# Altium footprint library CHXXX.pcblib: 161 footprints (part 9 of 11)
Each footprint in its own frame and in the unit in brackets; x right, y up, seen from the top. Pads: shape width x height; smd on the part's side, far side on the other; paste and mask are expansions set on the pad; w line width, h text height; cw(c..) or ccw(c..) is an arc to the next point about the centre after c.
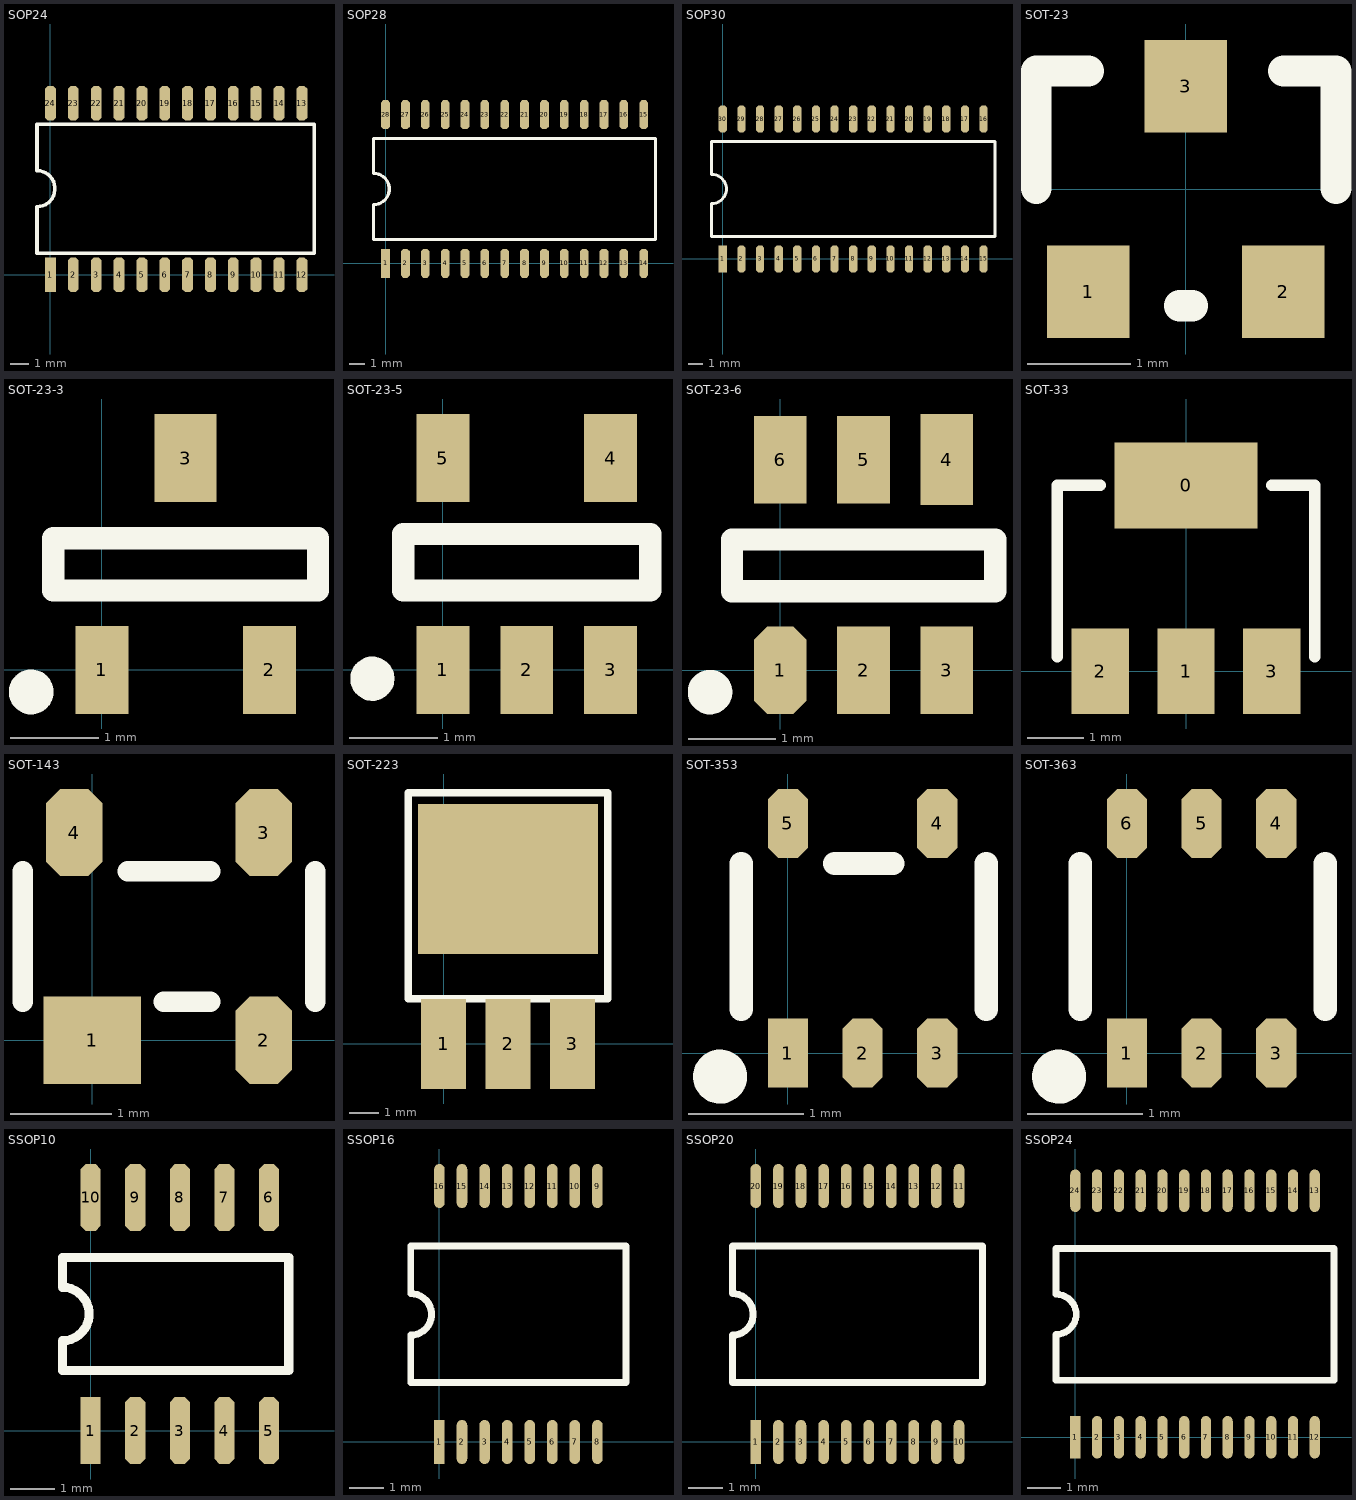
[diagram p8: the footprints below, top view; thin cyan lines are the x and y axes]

## SOP24 [mm]
pads (24):
  rect 0.6x1.905 smd: 1(0,0)
  oct 0.6x1.905 smd: 2(1.27,0) 3(2.54,0) 4(3.81,0) 5(5.08,0) 6(6.35,0) 7(7.62,0) 8(8.89,0) 9(10.16,0) 10(11.43,0) 11(12.7,0) 12(13.97,0) 13(13.97,9.525) 14(12.7,9.525) 15(11.43,9.525) 16(10.16,9.525) 17(8.89,9.525) 18(7.62,9.525) 19(6.35,9.525) 20(5.08,9.525) 21(3.81,9.525) 22(2.54,9.525) 23(1.27,9.525) 24(0,9.525)
TopOverlay:
  lines w0.2: -0.747,1.191 -0.747,3.78 ccw(c-0.747,4.78) -0.747,5.78 -0.747,8.368 14.653,8.368 14.653,1.191 -0.747,1.191

## SOP28 [mil]
pads (28):
  rect 22x72 smd: 1(0,0)
  oct 22x72 smd: 2(50,0) 3(100,0) 4(150,0) 5(200,0) 6(250,0) 7(300,0) 8(350,0) 9(400,0) 10(450,0) 11(500,0) 12(550,0) 13(600,0) 14(650,0) 15(650,375) 16(600,375) 17(550,375) 18(500,375) 19(450,375) 20(400,375) 21(350,375) 22(300,375) 23(250,375) 24(200,375) 25(150,375) 26(100,375) 27(50,375) 28(0,375)
TopOverlay:
  lines w8: -30,147.63 -30,60 680,60 680,315 -30,315 -30,226.87 cw(c-30,187.5) -30,148.13

## SOP30 [mil]
pads (30):
  rect 22x72 smd: 1(0,0)
  oct 22x72 smd: 2(50,0) 3(100,0) 4(150,0) 5(200,0) 6(250,0) 7(300,0) 8(350,0) 9(400,0) 10(450,0) 11(500,0) 12(550,0) 13(600,0) 14(650,0) 15(700,0) 16(700,375) 17(650,375) 18(600,375) 19(550,375) 20(500,375) 21(450,375) 22(400,375) 23(350,375) 24(300,375) 25(250,375) 26(200,375) 27(150,375) 28(100,375) 29(50,375) 30(0,375)
TopOverlay:
  lines w8: -30,60 -30,148.13 ccw(c-30,187.5) -30,226.87 -30,315 730,315 730,60 -30,60

## SOT-23 [mm]
height 1.3
pads (3):
  rect 0.8x0.9 smd: 1(-0.95,-1) 2(0.95,-1) 3(0,1)
TopOverlay:
  lines w0.305: -1.458,0.006 -1.458,1.149 -0.95,1.149 ; -0.061,-1.137 0.066,-1.137 ; 0.955,1.149 1.463,1.149 1.463,0.006

## SOT-23-3 [mm] "SOT-23-3"
pads (3):
  rect 0.6x1 smd: 1(0,0) 2(1.9,0)
  rect 0.7x1 smd: 3(0.95,2.4)
TopOverlay:
  circle w0.254: c-0.8,-0.25 r0.127
  lines w0.254: -0.55,0.9 2.45,0.9 2.45,1.49 -0.55,1.49 -0.55,0.9

## SOT-23-5 [mm]
pads (5):
  rect 0.6x1 smd: 1(0,0) 2(0.95,0) 3(1.9,0) 4(1.9,2.4) 5(0,2.4)
TopOverlay:
  circle w0.25: c-0.8,-0.1 r0.125
  lines w0.254: -0.45,0.9 2.35,0.9 2.35,1.54 -0.45,1.54 -0.45,0.9

## SOT-23-6 [mm] "SOT-23-6"
pads (6):
  oct 0.6x1 smd: 1(0,0)
  rect 0.6x1 smd: 2(0.95,0) 3(1.9,0) 5(0.95,2.4) 6(0,2.4)
  rect 0.6x1.04 smd: 4(1.9,2.4)
TopOverlay:
  circle w0.254: c-0.8,-0.25 r0.127
  lines w0.254: -0.55,0.9 2.45,0.9 2.45,1.49 -0.55,1.49 -0.55,0.9

## SOT-33 [mil]
pads (4):
  rect 100x60 smd: 0(0,130)
  rect 40x60 smd: 1(0,0) 2(-60,0) 3(60,0)
TopOverlay:
  lines w8: -90,10 -90,130 -60,130 ; 60,130 90,130 90,10

## SOT-143 [mil]
pads (4):
  rect 38x34 smd: 1(0,0)
  oct 22x34 smd: 2(67,0) 3(67,81) 4(-7,81)
TopOverlay:
  lines w8: -27,15 -27,66 ; 14,66 46,66 ; 28,15 46,15 ; 87,15 87,66

## SOT-223 [mil]
pads (4):
  rect 60x120 smd: 1(0,0) 2(86,0) 3(172,0)
  rect 240x200 smd: ""(86,220)
TopOverlay:
  lines w10: -47,60 -47,335 219,335 219,60 -47,60

## SOT-353 [mm]
pads (5):
  rect 0.35x0.6 smd mask+0.051: 1(0,0)
  oct 0.35x0.6 smd mask+0.051: 2(0.65,0) 3(1.3,0) 4(1.3,2) 5(0,2)
TopOverlay:
  circle w0.254: c-0.59,-0.205 r0.108
  lines w0.203: -0.406,0.381 -0.406,1.651 ; 0.406,1.651 0.914,1.651 ; 1.727,0.381 1.727,1.651

## SOT-363 [mm]
pads (6):
  rect 0.35x0.6 smd mask+0.051: 1(0,0)
  oct 0.35x0.6 smd mask+0.051: 2(0.65,0) 3(1.3,0) 4(1.3,2) 5(0.65,2) 6(0,2)
TopOverlay:
  circle w0.254: c-0.59,-0.205 r0.108
  lines w0.203: -0.406,0.381 -0.406,1.651 ; 1.727,0.381 1.727,1.651

## SSOP10 [mm]
pads (10):
  rect 0.45x1.5 smd: 1(0,0)
  oct 0.45x1.5 smd: 2(1,0) 3(2,0) 4(3,0) 5(4,0) 6(4,5.232) 7(3,5.232) 8(2,5.232) 9(1,5.232) 10(0,5.232)
TopOverlay:
  lines w0.203: -0.635,1.346 -0.635,2.016 ccw(c-0.635,2.616) -0.635,3.216 -0.635,3.886 4.445,3.886 4.445,1.346 -0.635,1.346

## SSOP16 [mil]
pads (16):
  rect 12x50 smd: 1(0,0)
  oval 12x50 smd: 2(25.6,0) 3(51.2,0) 4(76.8,0) 5(102.4,0) 6(128,0) 7(153.5,0) 8(179.1,0) 9(179.1,290) 10(153.5,290) 11(128,290) 12(102.4,290) 13(76.8,290) 14(51.2,290) 15(25.6,290) 16(0,290)
TopOverlay:
  lines w7.87: -32.48,67.24 211.61,67.24 211.61,221.97 -32.48,221.97 -32.48,168.23 cw(c-32.48,144.61) -32.48,120.98 -32.48,67.24

## SSOP20 [mil]
pads (20):
  rect 12x50 smd: 1(0,0)
  oval 12x50 smd: 2(25.6,0) 3(51.2,0) 4(76.8,0) 5(102.4,0) 6(128,0) 7(153.5,0) 8(179.1,0) 9(204.7,0) 10(230.3,0) 11(230.3,290) 12(204.7,290) 13(179.1,290) 14(153.5,290) 15(128,290) 16(102.4,290) 17(76.8,290) 18(51.2,290) 19(25.6,290) 20(0,290)
TopOverlay:
  lines w7.87: -26.57,67.24 -26.57,120.98 ccw(c-26.57,144.61) -26.57,168.23 -26.57,221.97 256.89,221.97 256.89,67.24 -26.57,67.24

## SSOP24 [mil]
pads (24):
  rect 12x50 smd: 1(0,0)
  oval 12x50 smd: 2(25.6,0) 3(51.2,0) 4(76.8,0) 5(102.4,0) 6(128,0) 7(153.5,0) 8(179.1,0) 9(204.7,0) 10(230.3,0) 11(256,0) 12(281.5,0) 13(281.5,290) 14(256,290) 15(230.3,290) 16(204.7,290) 17(179.1,290) 18(153.5,290) 19(128,290) 20(102.4,290) 21(76.8,290) 22(51.2,290) 23(25.6,290) 24(0,290)
TopOverlay:
  lines w7.87: -22.64,67.24 -22.64,120.98 ccw(c-22.64,144.61) -22.64,168.23 -22.64,221.97 304.13,221.97 304.13,67.24 -22.64,67.24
